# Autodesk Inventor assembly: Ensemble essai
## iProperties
Shininess: 41.0
Length Units: 11269
Angle Units: 11279
Time Units: 11290
Mass Units: 11283
Length Display Precision: 3
Angle Display Precision: 2
Created: 2002-03
Part Number: Ensemble essai
Document SubType Name: Assemblage
Designer: BAVERGE
Density: 0.0
Volumn: 0.0
Area: 0.0
PropertySet Name: Model Information
Control State: 0
Master: False
Checked Out: False
Author: BAVERGE
